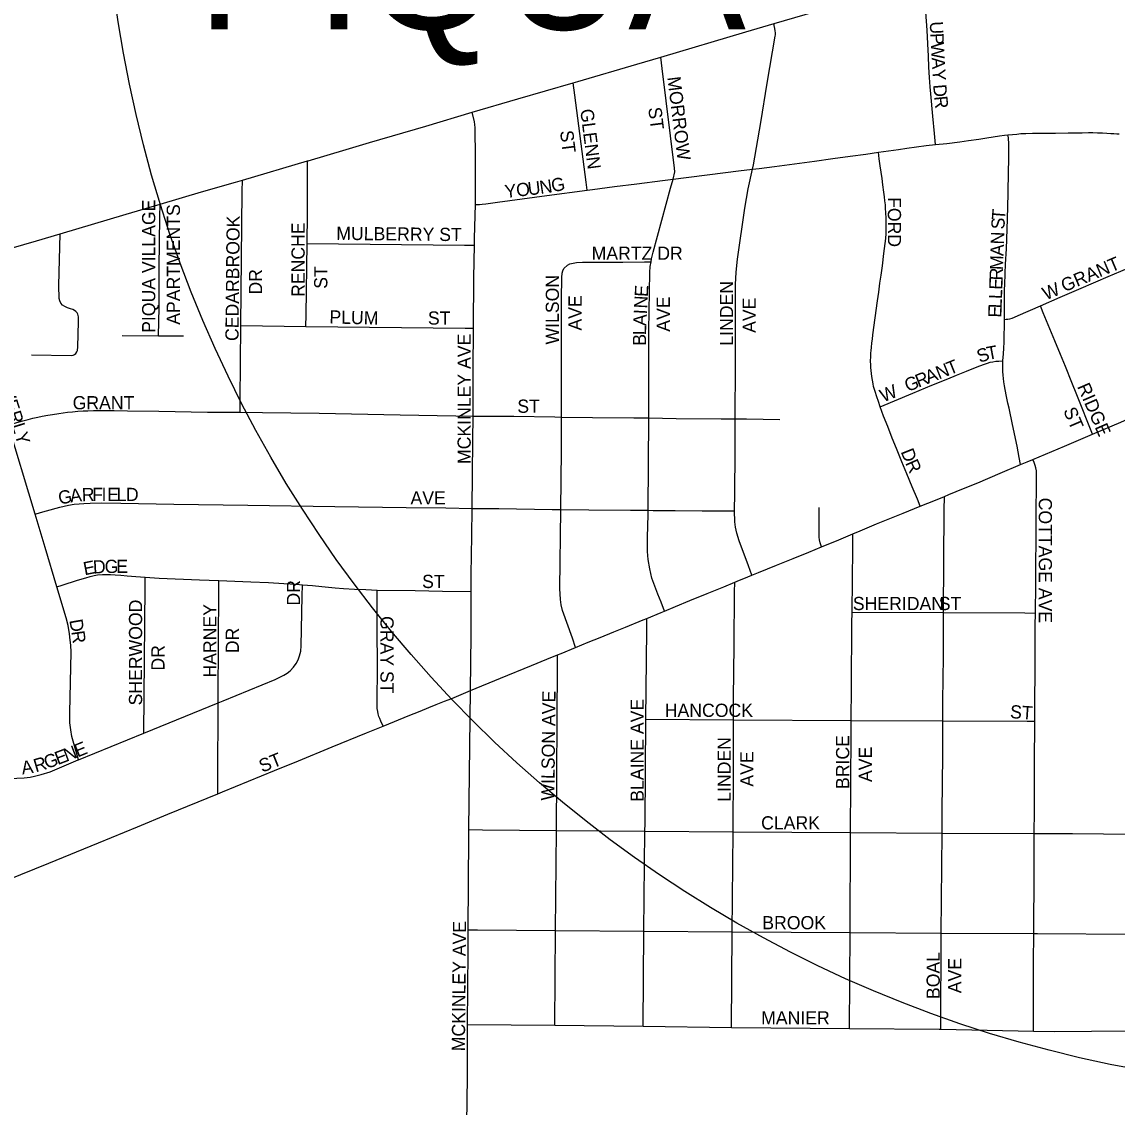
# Model space of a CAD drawing. Extents: x -87 to 2145, y -2128 to 440.
# Drawn here: x 266.02 to 286.77, y -573.52 to -552.95 of the extents above; entities that cross this region are included whole.
import ezdxf

# ---------------------------------------------------------------- set-up
doc = ezdxf.new("R2010")
doc.units = 0
for name, color, linetype in [('Default', 7, 'Continuous'), ('GM_X_City_Street', 7, 'Continuous'), ('GM_X_City_Street_Text', 7, 'Continuous'), ('GM_X_County_Road', 7, 'Continuous'), ('GM_X_US_Route', 7, 'Continuous')]:
    doc.layers.add(name, color=color, linetype=linetype)

msp = doc.modelspace()

# ---------------------------------------------------------------- linework, layer by layer
at = {"layer": 'Default'}
msp.add_circle((291.454, -549.312), 23.883, dxfattribs=at)
at = {"layer": 'GM_X_City_Street'}
for points in [[(283.331, -555.275), (283.312, -555.062), (283.278, -554.736), (283.241, -554.312), (283.231, -554.178), (283.22, -554), (283.207, -553.806), (283.196, -553.595), (283.183, -553.364), (283.17, -553.106), (283.151, -552.763), (283.142, -552.632), (283.135, -552.554), (283.127, -552.474), (283.12, -552.413), (283.111, -552.348), (283.105, -552.311), (283.096, -552.27), (283.059, -552.163)], [(279.862, -555.74), (279.88, -555.657), (280.024, -554.855), (280.143, -554.112), (280.292, -553.218), (280.297, -553.191), (280.298, -553.153), (280.294, -553.119), (280.287, -553.073), (280.277, -553.015), (280.271, -552.979)], [(278.358, -555.93), (278.39, -555.79), (278.386, -555.721), (278.152, -553.834), (278.125, -553.615)], [(276.733, -556.137), (276.713, -555.988), (276.496, -554.336), (276.465, -554.104)], [(274.612, -556.411), (274.613, -555.401), (274.608, -555.076), (274.61, -555.013), (274.608, -554.954), (274.604, -554.896), (274.595, -554.843), (274.551, -554.656)], [(283.331, -555.275), (283.546, -555.251), (283.793, -555.22), (283.958, -555.199), (284.149, -555.173), (284.305, -555.147), (284.425, -555.127), (284.546, -555.11), (284.636, -555.098), (284.703, -555.09)], [(284.636, -558.587), (284.636, -558.147), (284.638, -558.099), (284.64, -558.012), (284.642, -557.935), (284.651, -557.717), (284.658, -557.543), (284.674, -557.248), (284.697, -556.69), (284.709, -556.2), (284.714, -555.777), (284.718, -555.571), (284.718, -555.222), (284.716, -555.189), (284.712, -555.143), (284.703, -555.09)], [(284.703, -555.09), (284.787, -555.081), (284.874, -555.073), (284.948, -555.065), (285.041, -555.063), (285.171, -555.06), (285.293, -555.058), (285.605, -555.055), (285.846, -555.053), (285.987, -555.051), (286.109, -555.049), (286.23, -555.047), (286.313, -555.047), (286.399, -555.049), (286.497, -555.053), (286.577, -555.058), (286.655, -555.061), (286.71, -555.064), (286.766, -555.068), (286.812, -555.07)], [(282.248, -555.418), (282.632, -555.364), (282.79, -555.342), (282.971, -555.318), (283.157, -555.294), (283.331, -555.275)], [(279.862, -555.74), (279.989, -555.724), (280.282, -555.687), (280.659, -555.637), (281.041, -555.585), (281.384, -555.539), (281.714, -555.496), (282.009, -555.453), (282.248, -555.418)], [(282.284, -560.244), (282.248, -560.146), (282.218, -560.055), (282.188, -559.957), (282.17, -559.896), (282.159, -559.857), (282.149, -559.807), (282.135, -559.738), (282.127, -559.673), (282.118, -559.614), (282.111, -559.557), (282.105, -559.501), (282.103, -559.449), (282.1, -559.377), (282.103, -559.291), (282.106, -559.23), (282.112, -559.174), (282.116, -559.117), (282.125, -559.034), (282.135, -558.961), (282.146, -558.879), (282.19, -558.559), (282.235, -558.238), (282.257, -558.071), (282.279, -557.902), (282.3, -557.748), (282.324, -557.572), (282.355, -557.338), (282.376, -557.151), (282.387, -557.056), (282.394, -556.96), (282.398, -556.867), (282.398, -556.771), (282.396, -556.676), (282.389, -556.563), (282.385, -556.485), (282.381, -556.413), (282.373, -556.34), (282.366, -556.264), (282.352, -556.174), (282.333, -556.036), (282.318, -555.916), (282.3, -555.797), (282.285, -555.679), (282.266, -555.543), (282.248, -555.418)], [(271.423, -557.15), (271.43, -556.589), (271.431, -555.755), (271.431, -555.584)], [(278.358, -555.93), (278.604, -555.897), (279.056, -555.841), (279.596, -555.774), (279.862, -555.74)], [(279.538, -560.472), (279.541, -559.446), (279.54, -558.448), (279.543, -557.923), (279.554, -557.693), (279.581, -557.447), (279.72, -556.476), (279.783, -556.114), (279.862, -555.74)], [(270.17, -558.704), (270.196, -556.161), (270.198, -555.945)], [(276.733, -556.137), (276.829, -556.125), (277.25, -556.071), (277.669, -556.017), (278.159, -555.956), (278.358, -555.93)], [(277.941, -557.495), (277.95, -557.442), (277.98, -557.316), (278.312, -556.098), (278.358, -555.93)], [(274.612, -556.411), (274.655, -556.412), (274.692, -556.41), (274.744, -556.405), (274.811, -556.399), (275.032, -556.368), (275.966, -556.24), (276.733, -556.137)], [(268.608, -558.897), (268.618, -558.361), (268.622, -557.608), (268.634, -556.643), (268.637, -556.403)], [(274.595, -557.183), (274.597, -557.048), (274.612, -556.411)], [(266.201, -559.258), (266.956, -559.27), (266.988, -559.264), (267.018, -559.251), (267.043, -559.231), (267.063, -559.204), (267.074, -559.174), (267.082, -559.109), (267.09, -558.633), (267.09, -558.537), (267.079, -558.489), (267.064, -558.46), (267.042, -558.435), (267.015, -558.417), (266.984, -558.401), (266.943, -558.388), (266.882, -558.366), (266.833, -558.344), (266.792, -558.317), (266.758, -558.281), (266.736, -558.238), (266.726, -558.19), (266.721, -557.944), (266.742, -556.965)], [(271.402, -558.719), (271.405, -558.504), (271.423, -557.15)], [(271.423, -557.15), (274.409, -557.182), (274.595, -557.183)], [(274.576, -558.756), (274.576, -558.743), (274.582, -557.799), (274.595, -557.183)], [(276.287, -557.623), (276.357, -557.557), (276.401, -557.536), (276.465, -557.52), (276.53, -557.511), (276.645, -557.505), (277.404, -557.501), (277.815, -557.496), (277.941, -557.495)], [(277.896, -560.455), (277.898, -560.129), (277.898, -558.8), (277.916, -557.701), (277.926, -557.587), (277.941, -557.495)], [(285.319, -558.331), (285.692, -558.165), (286.046, -558.013), (286.369, -557.876), (286.602, -557.777), (286.842, -557.672), (287.005, -557.601), (287.14, -557.54), (287.196, -557.516), (287.257, -557.492), (287.305, -557.475), (287.353, -557.461)], [(276.245, -560.438), (276.243, -559.317), (276.245, -558.203), (276.25, -557.793), (276.258, -557.712), (276.269, -557.664), (276.287, -557.623)], [(284.636, -558.587), (284.672, -558.586), (284.703, -558.584), (284.742, -558.577), (284.783, -558.564), (284.829, -558.545), (284.898, -558.514), (285.319, -558.331)], [(286.309, -560.761), (286.01, -560.017), (285.916, -559.784), (285.793, -559.481), (285.699, -559.253), (285.591, -558.992), (285.372, -558.462), (285.319, -558.331)], [(284.61, -559.374), (284.621, -559.238), (284.628, -559.132), (284.632, -559.017), (284.635, -558.87), (284.638, -558.742), (284.636, -558.587)], [(270.154, -560.349), (270.156, -560.119), (270.17, -558.704)], [(270.17, -558.704), (271.402, -558.719)], [(271.402, -558.719), (274.422, -558.754), (274.576, -558.756)], [(274.569, -560.42), (274.573, -559.553), (274.576, -558.756)], [(267.92, -558.89), (268.608, -558.897)], [(268.608, -558.897), (269.082, -558.902)], [(282.284, -560.244), (282.899, -559.985), (283.259, -559.835), (283.563, -559.711), (283.73, -559.644), (283.917, -559.568), (284.058, -559.512), (284.171, -559.468), (284.259, -559.436), (284.314, -559.416), (284.366, -559.401), (284.418, -559.39), (284.472, -559.381), (284.529, -559.377), (284.61, -559.374)], [(284.944, -561.341), (284.918, -561.207), (284.877, -560.993), (284.788, -560.578), (284.724, -560.27), (284.703, -560.178), (284.675, -560.046), (284.648, -559.917), (284.636, -559.848), (284.625, -559.771), (284.619, -559.709), (284.614, -559.644), (284.61, -559.575), (284.608, -559.505), (284.607, -559.441), (284.61, -559.374)], [(283.043, -562.128), (282.988, -561.997), (282.891, -561.76), (282.789, -561.515), (282.693, -561.287), (282.604, -561.066), (282.561, -560.958), (282.511, -560.836), (282.426, -560.617), (282.348, -560.419), (282.284, -560.244)], [(286.309, -560.761), (286.841, -560.533), (287.268, -560.349), (287.632, -560.188)], [(265.761, -560.592), (265.924, -560.545), (266.035, -560.512), (266.139, -560.484), (266.23, -560.46), (266.319, -560.441), (266.406, -560.423), (266.512, -560.404), (266.601, -560.389), (266.718, -560.371), (266.799, -560.36), (266.881, -560.349), (266.981, -560.339), (267.081, -560.33), (267.181, -560.323), (267.272, -560.319), (267.378, -560.315), (267.491, -560.315), (267.626, -560.313), (267.771, -560.315), (268.023, -560.319), (268.613, -560.33), (269.538, -560.345), (270.154, -560.349)], [(270.154, -560.349), (270.579, -560.352), (271.651, -560.363), (273.186, -560.397), (274.243, -560.414), (274.569, -560.42)], [(274.55, -562.169), (274.556, -561.521), (274.563, -560.883), (274.569, -560.42)], [(274.569, -560.42), (275.339, -560.424), (276.12, -560.436), (276.245, -560.438)], [(276.233, -562.19), (276.246, -561.071), (276.245, -560.438)], [(276.245, -560.438), (276.83, -560.446), (277.615, -560.451), (277.896, -560.455)], [(277.885, -562.206), (277.896, -560.455)], [(277.896, -560.455), (278.417, -560.463), (279.267, -560.47), (279.538, -560.472)], [(279.524, -562.216), (279.523, -562.196), (279.527, -561.9), (279.537, -561.099), (279.538, -560.472)], [(279.538, -560.472), (279.748, -560.473), (280.384, -560.482)], [(266.27, -562.278), (266.15, -561.879), (265.854, -560.894), (265.761, -560.592)], [(285.178, -561.244), (285.778, -560.989), (286.309, -560.761)], [(283.499, -561.943), (283.584, -561.908), (283.864, -561.794), (284.131, -561.683), (284.556, -561.505), (284.944, -561.341)], [(284.944, -561.341), (285.066, -561.29), (285.178, -561.244)], [(285.223, -564.155), (285.232, -563.611), (285.239, -562.39), (285.248, -561.576), (285.248, -561.504), (285.246, -561.456), (285.235, -561.404), (285.217, -561.357), (285.198, -561.3), (285.178, -561.244)], [(283.043, -562.128), (283.334, -562.011), (283.499, -561.943)], [(283.484, -564.142), (283.497, -562.202), (283.499, -561.943)], [(266.27, -562.278), (266.373, -562.249), (266.666, -562.167), (266.738, -562.147), (266.82, -562.128), (266.903, -562.11), (267.009, -562.093), (267.107, -562.082), (267.191, -562.075), (267.311, -562.071), (267.532, -562.067), (267.895, -562.071), (268.897, -562.093), (270.299, -562.108), (271.951, -562.132), (273.303, -562.151), (274.051, -562.162), (274.55, -562.169)], [(274.533, -563.746), (274.534, -563.424), (274.545, -562.689), (274.55, -562.169)], [(274.55, -562.169), (275.054, -562.173), (276.07, -562.188), (276.233, -562.19)], [(281.168, -562.901), (281.148, -562.82), (281.134, -562.768), (281.128, -562.718), (281.124, -562.668), (281.124, -562.619), (281.125, -562.57), (281.126, -562.495), (281.124, -562.31), (281.126, -562.156)], [(281.765, -562.653), (281.901, -562.596), (282.216, -562.465), (282.466, -562.362), (282.72, -562.258), (283.043, -562.128)], [(266.684, -563.658), (266.462, -562.914), (266.27, -562.278)], [(276.512, -564.805), (276.451, -564.632), (276.265, -564.108), (276.237, -563.996), (276.224, -563.899), (276.212, -563.687), (276.233, -562.197), (276.233, -562.19)], [(276.233, -562.19), (276.764, -562.195), (277.552, -562.201), (277.885, -562.206)], [(278.197, -564.116), (278.132, -563.95), (278.072, -563.797), (278.011, -563.646), (277.957, -563.491), (277.915, -563.315), (277.886, -563.137), (277.876, -562.99), (277.877, -562.862), (277.876, -562.714), (277.885, -562.292), (277.885, -562.206)], [(277.885, -562.206), (277.984, -562.208), (278.4, -562.208), (278.908, -562.216), (279.433, -562.216), (279.524, -562.216)], [(279.85, -563.437), (279.786, -563.262), (279.612, -562.784), (279.567, -562.642), (279.543, -562.527), (279.531, -562.428), (279.524, -562.216)], [(281.168, -562.901), (281.498, -562.765), (281.765, -562.653)], [(281.749, -564.14), (281.762, -562.921), (281.765, -562.653)], [(279.85, -563.437), (279.978, -563.386), (280.321, -563.247), (280.636, -563.119), (280.933, -562.997), (281.168, -562.901)], [(266.684, -563.658), (266.78, -563.627), (267.075, -563.532), (267.231, -563.484), (267.311, -563.46), (267.389, -563.443), (267.454, -563.432), (267.55, -563.423), (267.622, -563.421), (267.697, -563.423), (267.788, -563.428), (267.897, -563.436), (268.014, -563.447), (268.181, -563.462), (268.357, -563.473)], [(268.33, -566.432), (268.355, -563.66), (268.357, -563.473)], [(268.357, -563.473), (268.62, -563.49), (269.382, -563.527), (269.752, -563.54)], [(269.74, -565.856), (269.74, -565.724), (269.751, -563.727), (269.752, -563.54)], [(269.74, -565.856), (269.833, -565.818), (270.818, -565.413), (270.981, -565.334), (271.048, -565.294), (271.102, -565.251), (271.167, -565.177), (271.214, -565.11), (271.252, -565.039), (271.281, -564.963), (271.304, -564.877), (271.312, -564.773), (271.33, -563.835), (271.334, -563.617)], [(269.752, -563.54), (270.358, -563.562), (270.69, -563.577), (270.981, -563.592), (271.22, -563.608), (271.334, -563.617)], [(271.334, -563.617), (271.526, -563.634), (271.704, -563.653), (271.955, -563.679), (272.114, -563.69), (272.324, -563.701), (272.537, -563.71), (272.749, -563.72)], [(278.197, -564.116), (278.406, -564.03), (278.676, -563.917), (279.004, -563.783), (279.318, -563.654), (279.526, -563.569)], [(279.505, -566.178), (279.505, -565.77), (279.513, -564.771), (279.524, -563.755), (279.526, -563.569)], [(279.526, -563.569), (279.576, -563.549), (279.774, -563.468), (279.85, -563.437)], [(267.093, -566.937), (267.031, -566.717), (266.969, -566.497), (266.944, -566.368), (266.931, -566.238), (266.927, -566.042), (266.951, -564.897), (266.946, -564.764), (266.937, -564.666), (266.92, -564.545), (266.895, -564.393), (266.86, -564.246), (266.684, -563.658)], [(272.862, -566.3), (272.819, -566.203), (272.8, -566.156), (272.785, -566.112), (272.772, -566.067), (272.761, -566.019), (272.754, -565.965), (272.752, -565.904), (272.754, -565.802), (272.759, -565.229), (272.752, -564.387), (272.75, -563.805), (272.749, -563.72)], [(272.749, -563.72), (273.47, -563.729), (273.989, -563.74), (274.533, -563.746)], [(274.521, -565.623), (274.53, -564.574), (274.533, -563.746)], [(277.862, -564.255), (278.135, -564.142), (278.197, -564.116)], [(281.735, -566.19), (281.739, -565.559), (281.747, -564.346), (281.749, -564.14)], [(281.749, -564.14), (283.484, -564.142)], [(283.471, -566.197), (283.471, -565.915), (283.479, -565.309), (283.48, -565.08), (283.482, -564.346), (283.484, -564.142)], [(283.484, -564.142), (285.023, -564.153), (285.223, -564.155)], [(285.211, -566.203), (285.211, -566.057), (285.217, -565.029), (285.22, -564.39), (285.223, -564.155)], [(276.512, -564.805), (276.749, -564.707), (276.975, -564.616), (277.238, -564.51), (277.455, -564.421), (277.791, -564.284), (277.862, -564.255)], [(277.845, -566.167), (277.86, -564.478), (277.862, -564.255)], [(276.171, -564.945), (276.237, -564.918), (276.51, -564.806), (276.512, -564.805)], [(274.521, -565.623), (275.088, -565.389), (275.676, -565.15), (275.964, -565.03), (276.171, -564.945)], [(276.147, -568.275), (276.17, -565.139), (276.171, -564.945)], [(272.862, -566.3), (273.082, -566.21), (273.338, -566.105), (273.565, -566.014), (273.733, -565.944), (273.871, -565.888), (274.028, -565.827), (274.167, -565.773), (274.521, -565.623)], [(274.491, -568.26), (274.491, -568.26), (274.521, -565.623)], [(268.33, -566.432), (269.74, -565.856)], [(269.734, -567.579), (269.735, -567.312), (269.74, -565.856)], [(269.734, -567.579), (269.819, -567.544), (270.805, -567.14), (271.26, -566.954), (271.898, -566.692), (272.551, -566.427), (272.862, -566.3)], [(277.825, -568.29), (277.828, -568.144), (277.845, -566.167)], [(277.845, -566.167), (279.505, -566.178)], [(279.494, -568.303), (279.504, -567.113), (279.505, -566.178)], [(279.505, -566.178), (281.735, -566.19)], [(281.722, -568.317), (281.733, -566.444), (281.735, -566.19)], [(281.735, -566.19), (283.471, -566.197)], [(283.457, -568.326), (283.458, -567.918), (283.47, -566.845), (283.471, -566.197)], [(283.471, -566.197), (285.071, -566.203), (285.211, -566.203)], [(285.201, -568.331), (285.204, -567.902), (285.21, -567.019), (285.211, -566.203)], [(267.093, -566.937), (268.33, -566.432)], [(265.64, -567.294), (265.786, -567.288), (266.064, -567.276), (266.174, -567.264), (266.259, -567.246), (266.386, -567.214), (266.555, -567.164), (267.088, -566.939), (267.093, -566.937)], [(265.609, -569.27), (265.997, -569.112), (266.528, -568.893), (267.468, -568.509), (268.212, -568.204), (268.788, -567.966), (269.734, -567.579)], [(274.476, -570.157), (274.476, -570.157), (274.49, -568.386), (274.491, -568.26)], [(274.491, -568.26), (274.746, -568.262), (276.147, -568.275)], [(276.132, -570.17), (276.147, -568.275)], [(276.147, -568.275), (277.825, -568.29)], [(277.802, -570.182), (277.825, -568.29)], [(277.825, -568.29), (279.494, -568.303)], [(279.479, -570.195), (279.494, -568.303)], [(279.494, -568.303), (281.722, -568.317)], [(281.711, -570.212), (281.722, -568.317)], [(281.722, -568.317), (283.457, -568.326)], [(283.44, -570.222), (283.457, -568.326)], [(283.457, -568.326), (285.201, -568.331)], [(285.192, -570.231), (285.193, -570.109), (285.2, -569.182), (285.2, -568.466), (285.201, -568.331)], [(285.201, -568.331), (285.93, -568.334), (287.694, -568.349)], [(274.461, -571.955), (274.473, -570.564), (274.476, -570.157)], [(274.476, -570.157), (274.655, -570.159), (276.132, -570.17)], [(276.116, -571.965), (276.132, -570.17)], [(276.132, -570.17), (277.802, -570.182)], [(277.791, -571.984), (277.802, -570.182)], [(277.802, -570.182), (279.479, -570.195)], [(279.467, -572.009), (279.479, -570.195)], [(279.479, -570.195), (281.711, -570.212)], [(281.699, -572.029), (281.711, -570.212)], [(281.711, -570.212), (283.44, -570.222)], [(283.43, -572.045), (283.44, -570.222)], [(283.44, -570.222), (285.192, -570.231)], [(285.187, -572.081), (285.187, -572.018), (285.186, -571.527), (285.188, -570.772), (285.192, -570.231)], [(285.192, -570.231), (285.263, -570.231), (287.099, -570.242), (287.68, -570.247)], [(274.461, -571.955), (276.116, -571.965)], [(274.461, -572.244), (274.461, -571.955)], [(276.116, -571.965), (277.791, -571.984)], [(277.791, -571.984), (279.467, -572.009)], [(279.467, -572.009), (281.699, -572.029)], [(281.699, -572.029), (283.4, -572.044), (283.43, -572.045)], [(283.43, -572.045), (285.187, -572.081)], [(285.187, -572.081), (285.591, -572.089), (287.672, -572.068)], [(274.461, -572.954), (274.461, -572.954), (274.461, -572.244)]]:
    msp.add_lwpolyline(points, dxfattribs=at)
at = {"layer": 'GM_X_County_Road'}
msp.add_lwpolyline([(274.437, -575.11), (274.44, -574.717), (274.461, -572.954)], dxfattribs=at)
at = {"layer": 'GM_X_US_Route'}
for points in [[(275.419, -554.406), (276.465, -554.104), (276.552, -554.079), (277.67, -553.75), (278.125, -553.615), (279.736, -553.136), (280.271, -552.979), (283.059, -552.163), (283.428, -552.054), (285.546, -551.437)], [(274.551, -554.656), (275.419, -554.406)], [(261.264, -558.569), (261.543, -558.487), (263.451, -557.923), (263.498, -557.91), (266.294, -557.098), (266.742, -556.965), (267.993, -556.594), (268.637, -556.403), (269.424, -556.17), (270.069, -555.983), (270.198, -555.945), (271.431, -555.584), (271.442, -555.581), (272.167, -555.364), (272.609, -555.235), (273.672, -554.924), (274.551, -554.656)]]:
    msp.add_lwpolyline(points, dxfattribs=at)

# ---------------------------------------------------------------- texts
at = {"layer": 'Default'}
msp.add_text('PIQUA', height=2.5, rotation=0, dxfattribs=at).set_placement((269.335, -553.09))
at = {"layer": 'GM_X_City_Street_Text'}
for s, rotation, p in [('U', 273.0829, (283.22, -552.945)), ('P', 273.0918, (283.232, -553.165)), ('W', 273.0856, (283.241, -553.341)), ('A', 273.0935, (283.257, -553.626)), ('Y', 273.0829, (283.269, -553.846)), ('MORROW', 277.1246, (278.248, -553.998)), ('D', 274.9956, (283.285, -554.141)), ('R', 275.7087, (283.305, -554.363)), ('GLENN', 277.2755, (276.598, -554.613)), ('ST', 277.1334, (277.887, -554.579)), ('ST', 277.1334, (276.215, -555.019)), ('N', 8.639, (275.847, -556.212)), ('G', 10.5554, (276.074, -556.177)), ('Y', 6.5502, (275.182, -556.289)), ('O', 6.5502, (275.4, -556.263)), ('U', 6.5502, (275.619, -556.238)), ('PIQUA VILLAGE', 90, (268.547, -558.843)), ('FORD', 270, (282.428, -556.269)), ('APARTMENTS', 90, (269.014, -558.689)), ('T', 85.7061, (284.645, -556.711)), ('CEDARBROOK', 89.4039, (270.124, -558.998)), ('RENCHE', 90, (271.378, -558.161)), ('S', 87.5674, (284.637, -556.885)), ('MULBERRY ST', 359.4074, (271.976, -557.08)), ('N', 87.9661, (284.627, -557.17)), ('A', 87.9671, (284.619, -557.39)), ('MARTZ DR', 0, (276.815, -557.458)), ('M', 87.9829, (284.61, -557.654)), ('GRANT', 22.8931, (285.773, -558.074)), ('ST', 90, (271.808, -558.007)), ('DR', 90, (270.571, -558.117)), ('WILSON', 90, (276.196, -559.063)), ('E', 87.978, (284.597, -558.028)), ('R', 87.9598, (284.603, -557.852)), ('E', 87.0623, (277.879, -558.165)), ('LINDEN', 90, (279.496, -559.085)), ('L', 87.983, (284.591, -558.204)), ('W', 22.6224, (285.421, -558.228)), ('AVE', 90, (276.626, -558.799)), ('N', 87.0481, (277.867, -558.385)), ('AVE', 90, (278.298, -558.821)), ('AVE', 90, (279.926, -558.843)), ('L', 87.9507, (284.584, -558.38)), ('PLUM', 358.5321, (271.844, -558.664)), ('ST', 0, (273.713, -558.686)), ('I', 87.0699, (277.862, -558.495)), ('E', 87.978, (284.578, -558.556)), ('A', 87.1572, (277.851, -558.715)), ('L', 88.5795, (277.846, -558.889)), ('MCKINLEY AVE', 90, (274.524, -561.329)), ('B', 89.9028, (277.846, -559.086)), ('S', 19.9901, (284.168, -559.416)), ('T', 10.383, (284.323, -559.358)), ('BEVERLY', 287.3016, (265.486, -559.511)), ('N', 21.8582, (283.396, -559.728)), ('T', 21.8744, (283.6, -559.646)), ('G', 21.8582, (282.804, -559.966)), ('R', 21.8622, (283.008, -559.884)), ('A', 21.8582, (283.192, -559.81)), ('W', 22.6224, (282.341, -560.164)), ('RIDGE', 293.5494, (286.01, -559.859)), ('GRANT', 0, (266.981, -560.292)), ('ST', 0, (275.407, -560.358)), ('ST', 293.1873, (285.747, -560.314)), ('D', 291.6512, (282.668, -561.094)), ('R', 293.9736, (282.753, -561.309)), ('G', 9.7965, (266.731, -562.097)), ('A', 7.0112, (266.944, -562.06)), ('R', 0.9714, (267.156, -562.034)), ('F', 0, (267.353, -562.03)), ('I', 0, (267.529, -562.03)), ('E', 0, (267.639, -562.03)), ('L', 0, (267.815, -562.03)), ('D', 0, (267.991, -562.03)), ('AVE', 0, (273.383, -562.096)), ('COTTAGE AVE', 270, (285.288, -561.967)), ('E', 11.2724, (267.209, -563.44)), ('D', 3.1265, (267.372, -563.407)), ('G', 0.2405, (267.588, -563.395)), ('E', 0, (267.808, -563.394)), ('DR', 90, (271.29, -564.013)), ('ST', 0, (273.603, -563.68)), ('SHERWOOD', 90, (268.298, -565.905)), ('HARNEY', 90, (269.707, -565.377)), ('SHERIDAN', 0, (281.765, -564.098)), ('ST', 0, (283.393, -564.098)), ('GRAY ST', 270, (272.814, -564.211)), ('D', 279.908, (266.917, -564.291)), ('DR', 90, (270.132, -564.915)), ('R', 277.9687, (266.955, -564.505)), ('DR', 90, (268.723, -565.245)), ('WILSON AVE', 89.3316, (276.108, -567.709)), ('BLAINE AVE', 90, (277.802, -567.731)), ('HANCOCK', 0, (278.201, -566.122)), ('ST', 356.1879, (284.738, -566.145)), ('LINDEN', 90, (279.452, -567.731)), ('BRICE', 90, (281.696, -567.489)), ('E', 20.5833, (266.698, -567.037)), ('N', 20.8579, (266.864, -566.974)), ('E', 22.2306, (267.075, -566.894)), ('AVE', 90, (282.126, -567.357)), ('A', 8.5243, (266.028, -567.215)), ('R', 16.3259, (266.282, -567.174)), ('G', 20.095, (266.489, -567.113)), ('ST', 21.8039, (270.572, -567.182)), ('AVE', 90, (279.882, -567.445)), ('CLARK', 0, (280.027, -568.256)), ('MCKINLEY AVE', 89.458, (274.414, -572.462)), ('BROOK', 0, (280.049, -570.148)), ('BOAL', 90, (283.412, -571.471)), ('AVE', 90, (283.82, -571.361)), ('MANIER', 0, (280.027, -571.952))]:
    msp.add_text(s, height=0.25, rotation=rotation, dxfattribs=at).set_placement(p)

doc.saveas('drawing.dxf')
